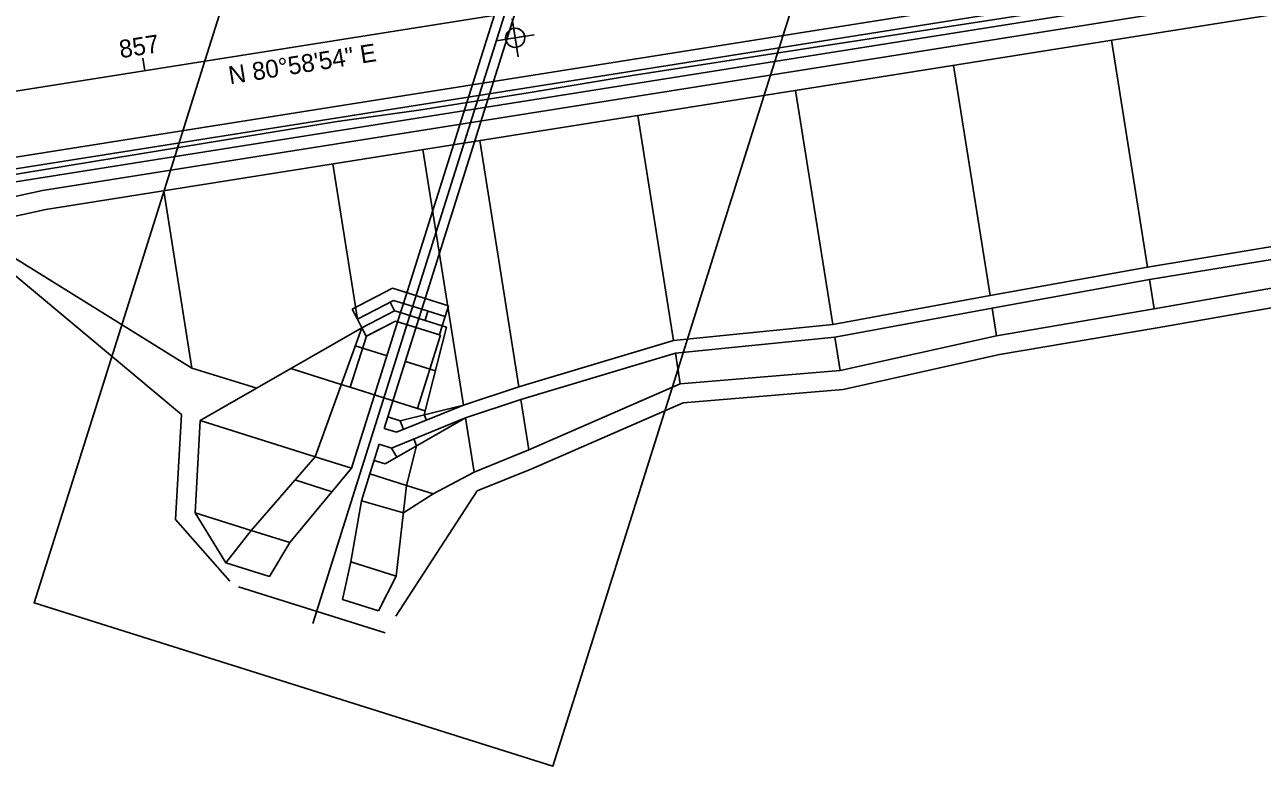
# Model space of a CAD drawing. Extents: x 115987 to 120394, y 324408 to 325987.
# Drawn here: x 117231.2 to 117424.6, y 325339.5 to 325455.4 of the extents above; entities that cross this region are included whole.
import ezdxf

# ---------------------------------------------------------------- set-up
doc = ezdxf.new("R2010")
doc.units = 0
for name, color, linetype in [('DR_Ditch', 7, 'Continuous'), ('DR_X_Headwall', 7, 'Continuous'), ('DT_X_Break_Line', 7, 'Continuous'), ('DT_X_Contour_Major', 7, 'Continuous'), ('DT_X_Contour_Minor', 7, 'Continuous'), ('DT_X_Contour_Text', 7, 'Continuous'), ('DT_X_Terrain_Boundary', 7, 'Continuous'), ('DT_X_Terrain_Ground_Line', 7, 'Continuous'), ('DT_X_Triangles', 7, 'Continuous'), ('PV_X_EOP', 7, 'Continuous'), ('PV_X_Shoulder', 7, 'Continuous'), ('RW_X_CL_100_Cardinal_Points', 7, 'Continuous'), ('RW_X_CL_100_Stations', 7, 'Continuous'), ('RW_X_CL_500_Stations', 7, 'Continuous'), ('RW_X_Esmt_LA', 7, 'Continuous'), ('SV_X_Break_Lines', 7, 'Continuous'), ('UT_X_Gas_Cells', 7, 'Continuous')]:
    doc.layers.add(name, color=color, linetype=linetype)

msp = doc.modelspace()

# ---------------------------------------------------------------- linework, layer by layer
at = {"layer": 'DR_Ditch'}
for p, q in [((117282.4, 325410.96), (117288.69, 325414.24)), ((117288.69, 325414.24), (117297.44, 325411.48)), ((117282.4, 325410.96), (117283.2, 325409.41)), ((117283.2, 325409.41), (117288.85, 325412.35)), ((117283.9, 325408.08), (117289, 325410.73)), ((117288.3, 325412.06), (117289, 325410.73)), ((117288.85, 325412.35), (117290.4, 325411.86)), ((117289, 325410.73), (117289.95, 325410.43)), ((117290.4, 325411.86), (117293.26, 325410.96)), ((117293.26, 325410.96), (117296.92, 325409.81)), ((117297.44, 325411.48), (117296.92, 325409.81)), ((117283.2, 325409.41), (117283.9, 325408.08)), ((117284.59, 325406.75), (117289.14, 325409.12)), ((117289.14, 325409.12), (117296.02, 325406.95)), ((117292.81, 325409.53), (117289.95, 325410.43)), ((117292.81, 325409.53), (117296.47, 325408.38)), ((117294.22, 325410.66), (117293.77, 325409.23)), ((117296.92, 325409.81), (117296.47, 325408.38)), ((117283.9, 325408.08), (117284.59, 325406.75)), ((117296.47, 325408.38), (117296.02, 325406.95))]:
    msp.add_line(p, q, dxfattribs=at)
at = {"layer": 'DR_X_Headwall'}
msp.add_lwpolyline([(117357.55, 325570.98), (117273.82, 325556.38), (117277.6, 325534.71), (117281.38, 325513.03), (117278.93, 325511.93), (117272.32, 325490.95), (117265.71, 325469.96), (117259.1, 325448.98), (117252.5, 325428), (117245.89, 325407.01), (117239.28, 325386.03), (117232.67, 325365.04), (117313.74, 325339.51), (117320.35, 325360.49), (117326.96, 325381.48), (117333.57, 325402.46), (117340.18, 325423.45), (117346.79, 325444.43), (117353.4, 325465.41), (117360.01, 325486.4), (117365.11, 325527.64), (117361.33, 325549.31)], close=True, dxfattribs=at)
at = {"layer": 'DT_X_Contour_Major'}
for p, q in [((117324.27, 325514.43), (117276.21, 325361.82)), ((117052.43, 325416.91), (117570.94, 325499.21))]:
    msp.add_line(p, q, dxfattribs=at)
at = {"layer": 'DT_X_Contour_Minor'}
msp.add_line((117202.77, 325426.6), (117400.3, 325457.95), dxfattribs=at)
at = {"layer": 'DT_X_Contour_Text'}
msp.add_circle((117300.24, 325438.12), 0.05, dxfattribs=at)
at = {"layer": 'DT_X_Terrain_Boundary'}
msp.add_line((117249.96, 325448.26), (117249.64, 325450.24), dxfattribs=at)
at = {"layer": 'DT_X_Terrain_Ground_Line'}
for p, q in [((117290.4, 325411.86), (117319.54, 325504.38)), ((117293.26, 325410.96), (117322.4, 325503.48)), ((117290.4, 325411.86), (117289.95, 325410.43)), ((117293.26, 325410.96), (117292.81, 325409.53))]:
    msp.add_line(p, q, dxfattribs=at)
at = {"layer": 'DT_X_Triangles'}
for p, q in [((117202.17, 325430.35), (117399.7, 325461.7)), ((117202.45, 325428.57), (117399.98, 325459.92))]:
    msp.add_line(p, q, dxfattribs=at)
at = {"layer": 'PV_X_EOP'}
for p, q in [((117234.5, 325426.57), (117468.89, 325463.77)), ((117401.08, 325453.01), (117406.71, 325417.56)), ((117376.39, 325449.09), (117382.1, 325413.1)), ((117351.7, 325445.17), (117357.5, 325408.59)), ((117327.01, 325441.25), (117332.59, 325406.08)), ((117293.43, 325435.92), (117299.77, 325395.96)), ((117302.32, 325437.33), (117308.43, 325398.81)), ((117279.35, 325433.69), (117283.2, 325409.41)), ((117252.93, 325429.5), (117257.34, 325401.74)), ((117218.2, 325422.97), (117234.5, 325426.57)), ((117229.25, 325419.21), (117257.34, 325401.74)), ((117407.74, 325411.03), (117407.02, 325415.59)), ((117407.74, 325411.03), (117432.37, 325415.35)), ((117383.1, 325406.83), (117382.41, 325411.13)), ((117383.1, 325406.83), (117407.74, 325411.03)), ((117258.64, 325393.56), (117283.9, 325408.08)), ((117283.9, 325408.08), (117276.57, 325387.91)), ((117297.1, 325408.18), (117293.65, 325394.45)), ((117296.47, 325408.38), (117297.1, 325408.18)), ((117282.87, 325405.26), (117287.83, 325403.69)), ((117358.64, 325401.4), (117357.82, 325406.61)), ((117358.64, 325401.4), (117383.1, 325406.83)), ((117333.66, 325399.32), (117332.9, 325404.11)), ((117257.34, 325401.74), (117267.46, 325398.63)), ((117272.78, 325401.69), (117280.67, 325399.2)), ((117295.38, 325401.32), (117290.69, 325402.79)), ((117333.66, 325399.32), (117358.64, 325401.4)), ((117280.67, 325399.2), (117282.08, 325398.76)), ((117309.99, 325388.98), (117333.66, 325399.32)), ((117289.86, 325393.52), (117299.77, 325395.96)), ((117292.57, 325395.45), (117293.81, 325395.07)), ((117309.99, 325388.98), (117308.74, 325396.83)), ((117258.64, 325393.56), (117257.83, 325379.14)), ((117258.64, 325393.56), (117276.57, 325387.91)), ((117287.53, 325386.79), (117300.08, 325393.99)), ((117287.96, 325394.12), (117289.86, 325393.52)), ((117290.41, 325392.18), (117289.86, 325393.52)), ((117293.99, 325393.63), (117293.65, 325394.45)), ((117301.43, 325385.51), (117300.08, 325393.99)), ((117292.43, 325389.6), (117290.87, 325383.41)), ((117291.99, 325390.68), (117292.43, 325389.6)), ((117276.57, 325387.91), (117266.61, 325376.37)), ((117276.57, 325387.91), (117282.29, 325386.11)), ((117289.35, 325387.83), (117288.53, 325389.26)), ((117301.43, 325385.51), (117309.99, 325388.98)), ((117285.82, 325387.33), (117287.53, 325386.79)), ((117273.43, 325384.27), (117279.25, 325382.44)), ((117290.87, 325383.41), (117285.15, 325385.21)), ((117295.02, 325382.1), (117301.43, 325385.51)), ((117290.87, 325383.41), (117289.23, 325369.25)), ((117290.38, 325379.11), (117295.02, 325382.1)), ((117295.02, 325382.1), (117290.87, 325383.41)), ((117290.38, 325379.11), (117283.82, 325380.99)), ((117257.83, 325379.14), (117266.61, 325376.37)), ((117262.64, 325371.33), (117257.83, 325379.14)), ((117266.61, 325376.37), (117262.64, 325371.33)), ((117266.61, 325376.37), (117272.65, 325374.47)), ((117289.23, 325369.25), (117282.19, 325371.47)), ((117289.23, 325369.25), (117286.49, 325363.82))]:
    msp.add_line(p, q, dxfattribs=at)
at = {"layer": 'PV_X_Shoulder'}
for p, q in [((117406.71, 325417.56), (117431.37, 325421.62)), ((117407.02, 325415.59), (117431.68, 325419.64)), ((117382.1, 325413.1), (117406.71, 325417.56)), ((117382.41, 325411.13), (117407.02, 325415.59)), ((117357.5, 325408.59), (117382.1, 325413.1)), ((117357.82, 325406.61), (117382.41, 325411.13)), ((117289.95, 325410.43), (117282.29, 325386.11)), ((117292.81, 325409.53), (117287.4, 325392.34)), ((117332.59, 325406.08), (117357.5, 325408.59)), ((117308.43, 325398.81), (117332.59, 325406.08)), ((117332.9, 325404.11), (117357.82, 325406.61)), ((117308.74, 325396.83), (117332.9, 325404.11)), ((117299.77, 325395.96), (117308.43, 325398.81)), ((117299.77, 325395.96), (117289.3, 325391.74)), ((117300.08, 325393.99), (117308.74, 325396.83)), ((117300.08, 325393.99), (117288.53, 325389.26)), ((117287.4, 325392.34), (117289.3, 325391.74)), ((117286.62, 325389.86), (117285.15, 325385.21)), ((117286.62, 325389.86), (117288.53, 325389.26)), ((117282.29, 325386.11), (117272.65, 325374.47)), ((117285.15, 325385.21), (117283.82, 325380.99)), ((117283.82, 325380.99), (117282.19, 325371.47)), ((117272.65, 325374.47), (117269.45, 325369.19)), ((117282.19, 325371.47), (117280.88, 325365.59))]:
    msp.add_line(p, q, dxfattribs=at)
at = {"layer": 'RW_X_CL_100_Cardinal_Points'}
for p, q in [((117284.6, 325406.75), (117289.14, 325409.12)), ((117289.14, 325409.12), (117296.18, 325406.9)), ((117296.18, 325406.9), (117292.57, 325395.45)), ((117282.08, 325398.76), (117284.6, 325406.75)), ((117292.57, 325395.45), (117282.08, 325398.76))]:
    msp.add_line(p, q, dxfattribs=at)
at = {"layer": 'RW_X_CL_100_Stations'}
for p, q in [((117262.64, 325371.33), (117269.45, 325369.19)), ((117286.49, 325363.82), (117280.88, 325365.59))]:
    msp.add_line(p, q, dxfattribs=at)
at = {"layer": 'RW_X_CL_500_Stations'}
for p, q in [((117307.87, 325453.4), (117307.4, 325456.37)), ((117307.87, 325453.4), (117304.9, 325452.93)), ((117306.38, 325453.17), (117307.87, 325453.4)), ((117307.87, 325453.4), (117307.63, 325454.88)), ((117307.87, 325453.4), (117310.83, 325453.87)), ((117309.35, 325453.64), (117307.87, 325453.4)), ((117307.87, 325453.4), (117308.34, 325450.44)), ((117307.87, 325453.4), (117308.1, 325451.92))]:
    msp.add_line(p, q, dxfattribs=at)
msp.add_circle((117307.87, 325453.4), 1.5, dxfattribs=at)
for start, end in [(9.0184, 99.0184), (189.0184, 279.0184)]:
    msp.add_arc((117307.87, 325453.4), 1.5, start, end, dxfattribs=at)
at = {"layer": 'RW_X_Esmt_LA'}
for p, q in [((117233.95, 325429.52), (117468.51, 325466.75)), ((117221.72, 325426.82), (117233.95, 325429.52))]:
    msp.add_line(p, q, dxfattribs=at)
at = {"layer": 'SV_X_Break_Lines'}
msp.add_lwpolyline([(117201.97, 325427.68), (117227.38, 325431.66), (117252.1, 325435.74), (117280.03, 325440.3), (117292.79, 325442.11), (117309.87, 325444.81), (117326.13, 325447.51), (117353.09, 325451.69), (117415.24, 325461.3), (117441.01, 325465.67), (117487.67, 325473.31)], dxfattribs=at)
at = {"layer": 'UT_X_Gas_Cells'}
for p, q in [((117229.72, 325416.24), (117255.68, 325394.49)), ((117408.21, 325408.07), (117432.84, 325412.39)), ((117383.57, 325403.87), (117408.21, 325408.07)), ((117359.12, 325398.44), (117383.57, 325403.87)), ((117334.13, 325396.35), (117359.12, 325398.44)), ((117310.46, 325386.02), (117334.13, 325396.35)), ((117255.68, 325394.49), (117254.76, 325378.08)), ((117301.9, 325382.55), (117310.46, 325386.02)), ((117301.9, 325382.55), (117289.21, 325362.96)), ((117263.27, 325368.44), (117254.76, 325378.08)), ((117264.62, 325367.56), (117287.52, 325360.35))]:
    msp.add_line(p, q, dxfattribs=at)

# ---------------------------------------------------------------- texts
at = {"layer": 'DT_X_Break_Line'}
msp.add_text('N 80°58\'54" E', height=2.8, rotation=9.0184, dxfattribs=at).set_placement((117263.28, 325446.12))
at = {"layer": 'DT_X_Terrain_Boundary'}
msp.add_text('857', height=2.8, rotation=9.0184, dxfattribs=at).set_placement((117246.19, 325450.2))

doc.saveas('drawing.dxf')
